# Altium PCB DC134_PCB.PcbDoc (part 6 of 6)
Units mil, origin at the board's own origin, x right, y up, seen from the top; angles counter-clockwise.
Board outline 4000 x 2750 mil, 6 copper layers (L1_Top Layer, L2_GND1, L3_Signal, L4_Plane, L5_GND2, L6_Bottom Layer), stack 57.7 mil thick; 399 components, 238 nets, 1523 pads, 671 vias.
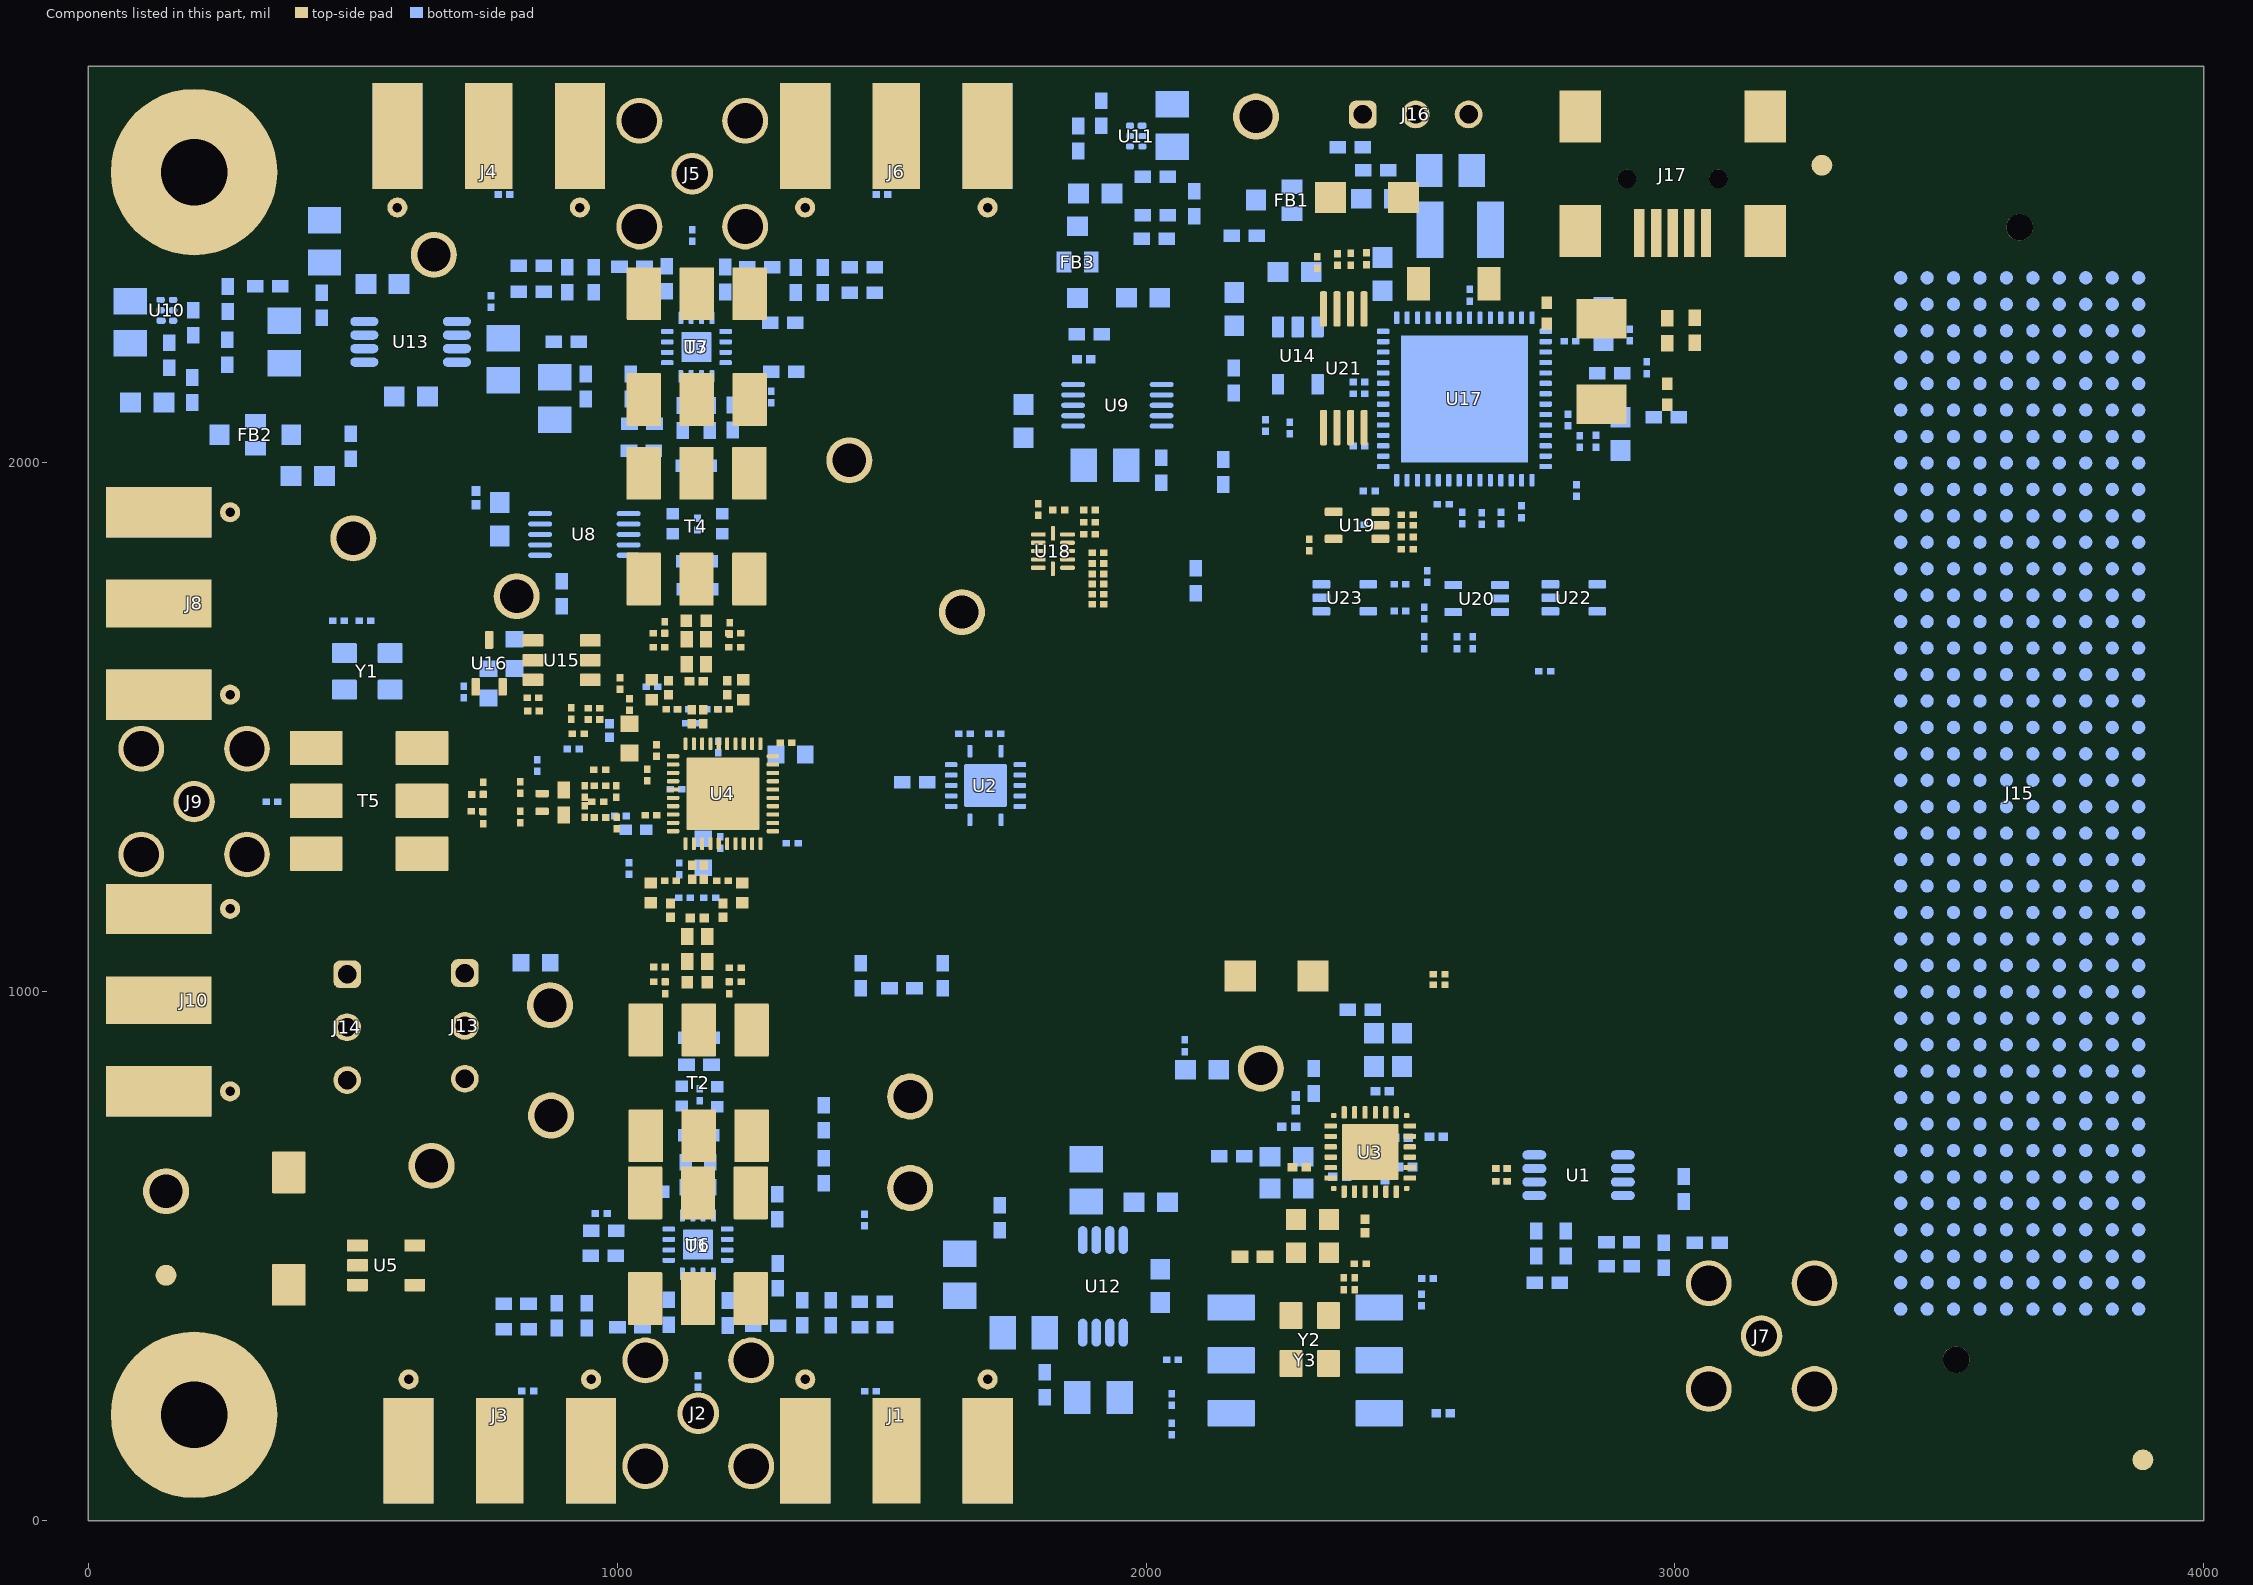
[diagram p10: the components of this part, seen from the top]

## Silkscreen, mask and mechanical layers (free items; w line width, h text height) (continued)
Drill Drawing:
  circle w10: c6400,-125.73 r16.58
  circle w10: c6400,-125.73 r27.63
  circle w10: c6400,-374.37 r27.63
  lines w10: 6372.37,-885.47 6386.18,-885.47 6386.18,-899.28 6413.81,-899.28 6413.81,-885.47 6427.62,-885.47 6427.62,-857.84 6413.81,-857.84 6413.81,-844.03 6386.18,-844.03 6386.18,-857.84 6372.37,-857.84 6372.37,-885.47 ; 6372.37,-774.96 6372.37,-761.15 6386.18,-747.33 6372.37,-733.52 6372.37,-719.71 6386.18,-719.71 6400,-733.52 6413.81,-719.71 6427.62,-719.71 6427.62,-733.52 6413.81,-747.33 6427.62,-761.15 6427.62,-774.96 6413.81,-774.96 6400,-761.15 6386.18,-774.96 6372.37,-774.96 ; 6372.37,-595.39 6427.62,-595.39 6400,-650.64 6372.37,-595.39 ; 6372.37,-512.51 6386.18,-512.51 6400,-526.32 6413.81,-512.51 6427.62,-512.51 6413.81,-498.69 6427.62,-484.88 6413.81,-484.88 6400,-471.07 6386.18,-484.88 6372.37,-484.88 6386.18,-498.69 6372.37,-512.51 ; 6372.37,-222.43 6427.62,-222.43 6400,-277.68 6372.37,-222.43 ; 6372.37,-29.04 6400,-15.23 6427.62,-29.04 6413.81,-1.41 6427.62,26.21 6400,12.4 6372.37,26.21 6386.18,-1.41 6372.37,-29.04 ; 6372.37,95.28 6372.37,109.09 6386.18,122.91 6372.37,136.72 6372.37,150.53 6386.18,150.53 6400,136.72 6413.81,150.53 6427.62,150.53 6427.62,136.72 6413.81,122.91 6427.62,109.09 6427.62,95.28 6413.81,95.28 6400,109.09 6386.18,95.28 6372.37,95.28 ; 6372.37,219.6 6427.62,219.6 6427.62,274.85 6372.37,274.85 6372.37,219.6 ; 6372.37,343.92 6427.62,343.92 6427.62,399.17 6372.37,399.17 6372.37,343.92 ; 6383.42,-879.94 6391.71,-879.94 6391.71,-888.23 6408.28,-888.23 6408.28,-879.94 6416.57,-879.94 6416.57,-863.37 6408.28,-863.37 6408.28,-855.08 6391.71,-855.08 6391.71,-863.37 6383.42,-863.37 6383.42,-879.94 ; 6383.42,-763.91 6383.42,-755.62 6391.71,-747.33 6383.42,-739.05 6383.42,-730.76 6391.71,-730.76 6400,-739.05 6408.28,-730.76 6416.57,-730.76 6416.57,-739.05 6408.28,-747.33 6416.57,-755.62 6416.57,-763.91 6408.28,-763.91 6400,-755.62 6391.71,-763.91 6383.42,-763.91 ; 6383.42,-606.44 6416.57,-606.44 6400,-639.59 6383.42,-606.44 ; 6383.42,354.97 6416.57,354.97 6416.57,388.12 6383.42,388.12 6383.42,354.97
  lines w12: 6322.28,-936.58 10696.95,-936.58 ; 6322.28,430.94 10696.95,430.94 ; 6660.14,-1060.9 6660.14,555.26 ; 6992.14,-1060.9 6992.14,555.26 ; 7628.7,-1060.9 7628.7,555.26 ; 7887.84,-1060.9 7887.84,555.26 ; 8263,-1060.9 8263,555.26 ; 8940.52,-1060.9 8940.52,555.26 ; 9378.29,-1060.9 9378.29,555.26 ; 10284.77,-1060.9 10284.77,555.26 ; 6322.28,-1060.9 10696.95,-1060.9 10696.95,555.26 6322.28,555.26 6322.28,-1060.9
  text "Symbol" at 6396.87,468.24 h72
  text "Quantity" at 6697.44,468.24 h72
  text "Finished Hole Size" at 7029.44,468.24 h72
  text "Plated" at 7666,468.24 h72
  text "Hole Type" at 7925.14,468.24 h72
  text "Routed Path Length" at 8300.3,468.24 h72
  text "Hole Length" at 8977.82,468.24 h72
  text "Drill Layer Pair" at 9415.58,468.24 h72
  text "Tolerance" at 10322.06,468.24 h72
  text "2" at 6697.44,343.92 h60
  text "35.43mil (0.900mm)" at 7029.44,343.92 h60
  text "NPTH" at 7666,343.92 h60
  text "Round" at 7925.14,343.92 h60
  text "-" at 8300.3,343.92 h60
  text "-" at 8977.82,343.92 h60
  text "L1_Top Layer - L6_Bottom Layer" at 9415.58,343.92 h60
  text "2" at 6697.44,219.6 h60
  text "50.00mil (1.270mm)" at 7029.44,219.6 h60
  text "NPTH" at 7666,219.6 h60
  text "Round" at 7925.14,219.6 h60
  text "-" at 8300.3,219.6 h60
  text "-" at 8977.82,219.6 h60
  text "L1_Top Layer - L6_Bottom Layer" at 9415.58,219.6 h60
  text "54" at 6697.44,95.28 h60
  text "7.87mil (0.200mm)" at 7029.44,95.28 h60
  text "PTH" at 7666,95.28 h60
  text "Round" at 7925.14,95.28 h60
  text "-" at 8300.3,95.28 h60
  text "-" at 8977.82,95.28 h60
  text "L1_Top Layer - L6_Bottom Layer" at 9415.58,95.28 h60
  text "+/- 3 mil" at 10322.06,95.28 h60
  text "434" at 6697.44,-29.04 h60
  text "8.00mil (0.203mm)" at 7029.44,-29.04 h60
  text "PTH" at 7666,-29.04 h60
  text "Round" at 7925.14,-29.04 h60
  text "-" at 8300.3,-29.04 h60
  text "-" at 8977.82,-29.04 h60
  text "L1_Top Layer - L6_Bottom Layer" at 9415.58,-29.04 h60
  text "183" at 6697.44,-153.36 h60
  text "10.00mil (0.254mm)" at 7029.44,-153.36 h60
  text "PTH" at 7666,-153.36 h60
  text "Round" at 7925.14,-153.36 h60
  text "-" at 8300.3,-153.36 h60
  text "-" at 8977.82,-153.36 h60
  text "L1_Top Layer - L6_Bottom Layer" at 9415.58,-153.36 h60
  text "+/- 3 mil" at 10322.06,-153.36 h60
  text "12" at 6697.44,-277.68 h60
  text "18.00mil (0.457mm)" at 7029.44,-277.68 h60
  text "PTH" at 7666,-277.68 h60
  text "Round" at 7925.14,-277.68 h60
  text "-" at 8300.3,-277.68 h60
  text "-" at 8977.82,-277.68 h60
  text "L1_Top Layer - L6_Bottom Layer" at 9415.58,-277.68 h60
  text "9" at 6697.44,-402 h60
  text "35.00mil (0.889mm)" at 7029.44,-402 h60
  text "PTH" at 7666,-402 h60
  text "Round" at 7925.14,-402 h60
  text "-" at 8300.3,-402 h60
  text "-" at 8977.82,-402 h60
  text "L1_Top Layer - L6_Bottom Layer" at 9415.58,-402 h60
  text "4" at 6697.44,-526.32 h60
  text "59.06mil (1.500mm)" at 7029.44,-526.32 h60
  text "PTH" at 7666,-526.32 h60
  text "Round" at 7925.14,-526.32 h60
  text "-" at 8300.3,-526.32 h60
  text "-" at 8977.82,-526.32 h60
  text "L1_Top Layer - L6_Bottom Layer" at 9415.58,-526.32 h60
  text "13" at 6697.44,-650.64 h60
  text "63.00mil (1.600mm)" at 7029.44,-650.64 h60
  text "PTH" at 7666,-650.64 h60
  text "Round" at 7925.14,-650.64 h60
  text "-" at 8300.3,-650.64 h60
  text "-" at 8977.82,-650.64 h60
  text "L1_Top Layer - L6_Bottom Layer" at 9415.58,-650.64 h60
  text "+/- 3 mil" at 10322.06,-650.64 h60
  text "16" at 6697.44,-774.96 h60
  text "66.93mil (1.700mm)" at 7029.44,-774.96 h60
  text "PTH" at 7666,-774.96 h60
  text "Round" at 7925.14,-774.96 h60
  text "-" at 8300.3,-774.96 h60
  text "-" at 8977.82,-774.96 h60
  text "L1_Top Layer - L6_Bottom Layer" at 9415.58,-774.96 h60
  text "2" at 6697.44,-899.28 h60
  text "125.98mil (3.200mm)" at 7029.44,-899.28 h60
  text "PTH" at 7666,-899.28 h60
  text "Round" at 7925.14,-899.28 h60
  text "-" at 8300.3,-899.28 h60
  text "-" at 8977.82,-899.28 h60
  text "L1_Top Layer - L6_Bottom Layer" at 9415.58,-899.28 h60
  text "731 Total" at 6697.44,-1023.6 h60
  text ".Layer_Name" at 577,-1885.49 h60
M17 Embedded Cavity:
  text ".Layer_Name" at 577,-1885.49 h60
M18 Embedded Assembly:
  text ".Layer_Name" at 577,-1885.49 h60
M19 Embedded Keepout:
  text ".Layer_Name" at 577,-1885.49 h60

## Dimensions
-25,0 to -25,2750 on M2 Board Dimensions
0,-25 to 4000,-25 on M2 Board Dimensions
0,-1427 to 1000,-1427 on M2 Board Dimensions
